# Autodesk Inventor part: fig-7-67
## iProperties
Shininess: 64.0
Length Units: 11269
Angle Units: 11279
Time Units: 11290
Mass Units: 11283
Length Display Precision: 3
Angle Display Precision: 2
Compacted: True
Part Number: fig-7-67
Document SubType Name: Modeling
Created: 2002-12
Designer: deepak
Density: 1 g/cm^3
Density: 0.0
Volumn: 0.0
Area: 0.0
PropertySet Name: Model Information
Control State: 0
Master: False
Checked Out: False
Author: deepak
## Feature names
1. Extrusion1
